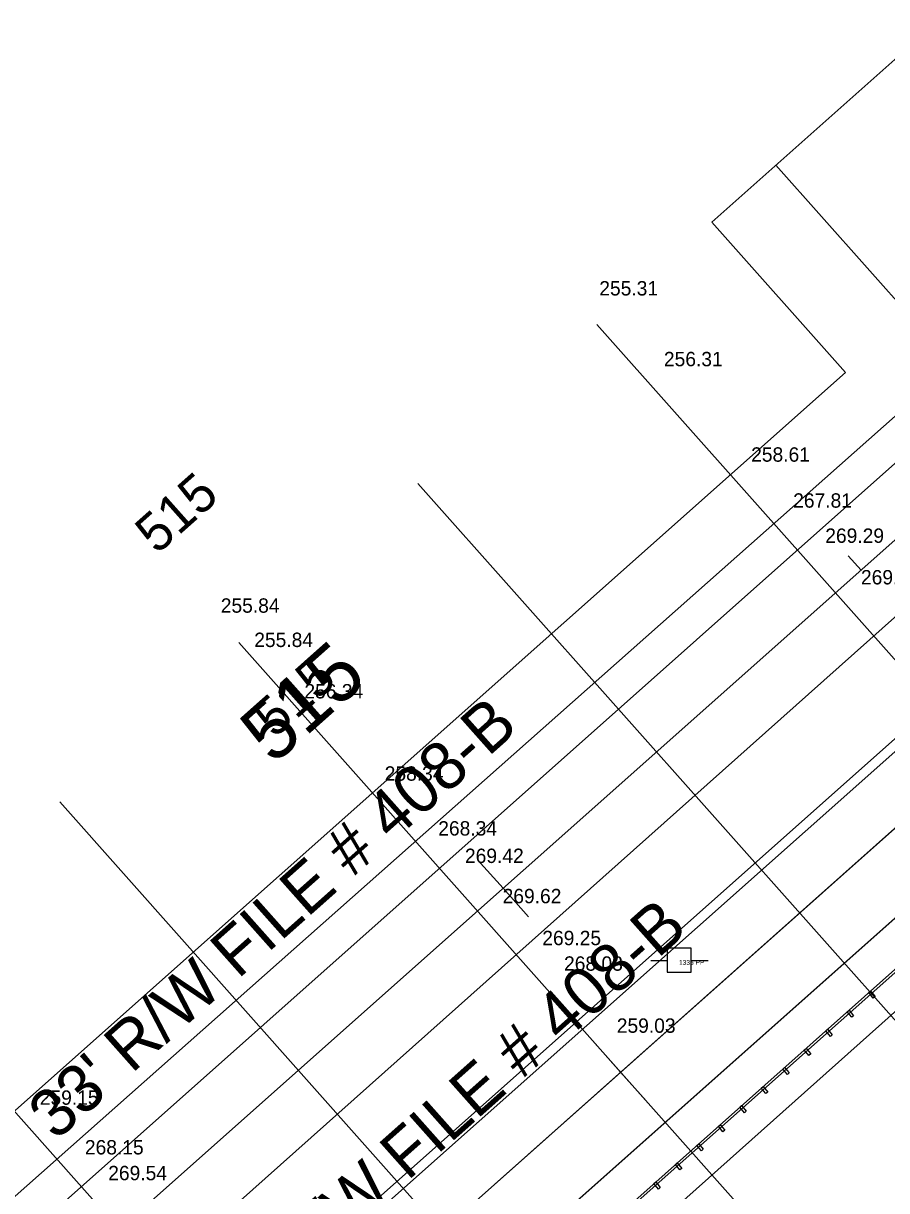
# Model space of a CAD drawing. Extents: x 49683 to 58852, y 49525 to 54803.
# Drawn here: x 53192.2 to 53372.4, y 51284.7 to 51528.4 of the extents above; entities that cross this region are included whole.
import ezdxf

# ---------------------------------------------------------------- set-up
doc = ezdxf.new("R2010")
doc.units = 0
for name, color, linetype in [('Level 1', 7, 'Continuous'), ('Level 11', 7, 'Continuous'), ('Level 13', 7, 'Continuous'), ('Level 19', 7, 'Continuous'), ('Level 20', 7, 'Continuous'), ('Level 21', 7, 'Continuous'), ('Level 25', 7, 'Continuous'), ('Level 27', 7, 'Continuous'), ('Level 29', 7, 'Continuous'), ('Level 3', 7, 'Continuous'), ('Level 32', 7, 'Continuous'), ('Level 50', 7, 'Continuous'), ('Level 59', 7, 'Continuous'), ('Level 63', 7, 'Continuous'), ('Level 9', 7, 'Continuous')]:
    doc.layers.add(name, color=color, linetype=linetype)

# ---------------------------------------------------------------- blocks, each defined once
blk = doc.blocks.new('PP')
at = {"layer": 'Level 9'}
for p, q in [((2.53, 2.45), (-2.47, 2.45)), ((-2.47, 2.45), (-2.47, -2.55)), ((2.53, -2.55), (2.53, 2.45)), ((-5.91, -0.11), (-2.44, -0.11)), ((2.45, -0.11), (6.09, -0.11)), ((-2.47, -2.55), (2.53, -2.55))]:
    blk.add_line(p, q, dxfattribs=at)

msp = doc.modelspace()

# ---------------------------------------------------------------- linework, layer by layer
at = {"layer": 'Level 1'}
for p, q in [((52544.81, 50683.3), (55534.58, 53340.86)), ((53367.09, 51414.21), (53364.43, 51417.2)), ((53292.35, 51347.78), (53287.03, 51353.76)), ((53297.66, 51341.8), (53292.35, 51347.78))]:
    msp.add_line(p, q, dxfattribs=at)
at = {"layer": 'Level 11'}
for p, q in [((53245.86, 51207.55), (53944.24, 51830.77)), ((53157.7, 51254.45), (53424.49, 51490.93))]:
    msp.add_line(p, q, dxfattribs=at)
at = {"layer": 'Level 13'}
for p, q in [((53573.51, 51698.05), (53335.95, 51486.88)), ((53335.95, 51486.88), (53363.85, 51455.49)), ((52637.37, 50809.73), (53363.85, 51455.49)), ((53407.7, 51406.16), (52566.74, 50658.64))]:
    msp.add_line(p, q, dxfattribs=at)
at = {"layer": 'Level 19'}
for p, q in [((52714.15, 50773.62), (54181.77, 52078.16)), ((53316.9, 51309.39), (53311.58, 51315.37)), ((53316.9, 51309.39), (53322.21, 51303.41))]:
    msp.add_line(p, q, dxfattribs=at)
at = {"layer": 'Level 20'}
for p, q in [((52704.85, 50784.08), (53476.26, 51469.77)), ((52723.45, 50763.15), (53495.78, 51449.66))]:
    msp.add_line(p, q, dxfattribs=at)
at = {"layer": 'Level 27'}
for p, q in [((52953.7, 50957.11), (53467.54, 51413.86)), ((52954.03, 50956.74), (53467.88, 51413.49))]:
    msp.add_line(p, q, dxfattribs=at)
for points in [[(53370.04, 51325.18), (53369.65, 51324.86), (53368.69, 51326.01), (53369.08, 51326.33)], [(53365.55, 51321.19), (53365.17, 51320.87), (53364.21, 51322.02), (53364.59, 51322.34)], [(53361.07, 51317.2), (53360.69, 51316.88), (53359.72, 51318.03), (53360.11, 51318.35)], [(53356.59, 51313.22), (53356.2, 51312.9), (53355.24, 51314.05), (53355.62, 51314.37)], [(53352.1, 51309.23), (53351.72, 51308.91), (53350.76, 51310.06), (53351.14, 51310.38)], [(53347.62, 51305.25), (53347.23, 51304.92), (53346.27, 51306.08), (53346.65, 51306.4)], [(53343.13, 51301.26), (53342.75, 51300.94), (53341.79, 51302.09), (53342.17, 51302.41)], [(53338.65, 51297.27), (53338.26, 51296.95), (53337.3, 51298.1), (53337.69, 51298.42)], [(53334.16, 51293.29), (53333.78, 51292.97), (53332.82, 51294.12), (53333.2, 51294.44)], [(53329.68, 51289.3), (53329.29, 51288.98), (53328.33, 51290.13), (53328.72, 51290.45)], [(53325.19, 51285.31), (53324.81, 51284.99), (53323.85, 51286.14), (53324.23, 51286.47)]]:
    msp.add_lwpolyline(points, close=True, dxfattribs=at)
at = {"layer": 'Level 29'}
for p, q in [((52714.15, 50773.62), (54181.77, 52078.16)), ((53316.9, 51309.39), (53311.58, 51315.37))]:
    msp.add_line(p, q, dxfattribs=at)
at = {"layer": 'Level 3'}
for p, q in [((53162.5, 51248.32), (53434.09, 51489.84)), ((53179.35, 51230.72), (53449.72, 51471.81))]:
    msp.add_line(p, q, dxfattribs=at)
at = {"layer": 'Level 50'}
for p, q in [((53349.29, 51498.74), (53508.73, 51319.36)), ((53311.92, 51465.52), (53471.36, 51286.14)), ((53274.55, 51432.3), (53433.99, 51252.92)), ((53237.18, 51399.08), (53396.62, 51219.7)), ((53199.8, 51365.86), (53359.25, 51186.48)), ((53162.43, 51332.65), (53321.88, 51153.27))]:
    msp.add_line(p, q, dxfattribs=at)
at = {"layer": 'Level 63'}
for p, q in [((52716.81, 50794.72), (53451.1, 51447.41)), ((53460.4, 51436.95), (52726.11, 50784.25)), ((53460.4, 51436.95), (52800.86, 50850.69)), ((52810.16, 50840.23), (53469.7, 51426.49))]:
    msp.add_line(p, q, dxfattribs=at)

# ---------------------------------------------------------------- block references
at = {"layer": 'Level 9'}
msp.add_blockref('PP', (53329.09, 51332.81), dxfattribs=at)

# ---------------------------------------------------------------- texts
at = {"layer": 'Level 19'}
msp.add_text('515', height=8, rotation=41.6334, dxfattribs=at).set_placement((53244.65, 51378.96))
at = {"layer": 'Level 21'}
for height, rotation, p in [(8, 41.6333, (53220.1, 51417.35)), (12, 41.6334, (53244.4, 51373.39))]:
    msp.add_text('515', height=height, rotation=rotation, dxfattribs=at).set_placement(p)
at = {"layer": 'Level 25'}
for p in [(53199, 51294.91), (53234.4, 51252.78)]:
    msp.add_text("33' R/W FILE # 408-B", height=10, rotation=41.6333, dxfattribs=at).set_placement(p)
at = {"layer": 'Level 32'}
for s, p in [('255.31', (53312.45, 51471.55)), ('256.31', (53325.94, 51456.78)), ('258.61', (53344.15, 51436.85)), ('267.81', (53352.92, 51427.25)), ('269.29', (53359.62, 51419.91)), ('269.53', (53367.08, 51411.23)), ('255.84', (53233.43, 51405.32)), ('255.84', (53240.42, 51398.16)), ('256.34', (53250.89, 51387.43)), ('258.34', (53267.65, 51370.25)), ('268.34', (53278.83, 51358.8)), ('269.42', (53284.41, 51353.07)), ('269.62', (53292.27, 51344.67)), ('269.25', (53300.55, 51335.91)), ('268.03', (53305.09, 51330.58)), ('259.03', (53316.1, 51317.62)), ('259.15', (53195.65, 51302.59)), ('268.15', (53205.06, 51292.22)), ('269.54', (53209.93, 51286.84))]:
    msp.add_text(s, height=3, dxfattribs=at).set_placement(p)
at = {"layer": 'Level 59'}
msp.add_text('1336 PP', height=1, dxfattribs=at).set_placement((53329.09, 51331.81))

doc.saveas('drawing.dxf')
